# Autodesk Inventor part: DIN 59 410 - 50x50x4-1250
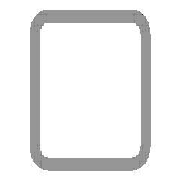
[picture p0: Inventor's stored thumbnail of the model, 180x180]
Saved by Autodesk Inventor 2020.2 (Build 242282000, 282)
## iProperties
Manager: www.cadconsulting.pl
Company: Fabian Stasiak CAD Consulting
IsCustomPart: 1
_CCFamilyMember: 40
_CCFamilyDisplayName: DIN 59410 (Kwadrat) - Rurki stalowe o przekroju kwadratowym formowane na gorąco
_FrameMemberDoc: Frame Member File
_Version: 15.0.0
_GetPNFromCC: 1
Created: 2015-01
Part Number: DIN 59 410 - 50x50x4-1250
Material: Stal, miękka
Description: Rurki stalowe o przekroju kwadratowym formowane na gorąco
Document SubType Name: Modellieren
Standard: DIN
Designer: F.Stasiak
Standards Organization: DIN
Language: pl-PL
Size Designation: 50x50x4
Categories: <MemberInstance><Categories><Category DisplayName="Kształtowniki konstrukcyjne" InternalName="089c4875-fa83-4c05-b084-43b9cc11f5ed" Mnemonic="GRDR"><CategoryPar
Stock Number: 50x50x4
Density: 7.85 g/cm^3
Appearance: Częściowo polerowana
Mass: 9798.37 g
Surface Area: 6261.29 cm^2
Volume: 1248.2 cm^3
Catalog Web Link: www.expertbooks.pl
G_W: 50,000 mm
G_H: 50,000 mm
+BD22D635-0862-4ED7-A4CA-62C603390CA0+CUTDETAIL2: Wytnij
+5BC96441-BBE8-4AF1-9985-3B583943D745+CUTDETAIL3: Wytnij
G_L: 1250,000 mm
Author: F.Stasiak
Subject: Zbiór ćwiczeń. Autodesk Inventor 2020. Kurs Professional
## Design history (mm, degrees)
node "Płaszczyzna początkowa"
node "Płaszczyzna końcowa"
sketch "Szkic1"
  geometry: L1 (-17, 25)-(17, 25); L2 (25, 17)-(25, -17); L3 (17, -25)-(-17, -25); L4 (-25, -17)-(-25, 17); L5 (-37.32, 0)-(37.32, 0) reference; L6 (0, -37.32)-(0, 37.32) reference; L7 (-17, 21)-(17, 21); L8 (21, 17)-(21, -17); L9 (17, -21)-(-17, -21); L10 (-21, -17)-(-21, 17); A1 r 8 centre (-17, 17) between (-17, 25) and (-25, 17); A2 r 8 centre (17, 17) between (25, 17) and (17, 25); A3 r 8 centre (17, -17) between (17, -25) and (25, -17); A4 r 8 centre (-17, -17) between (-25, -17) and (-17, -25); A5 r 4 centre (-17, 17) between (-17, 21) and (-21, 17); A6 r 4 centre (17, 17) between (21, 17) and (17, 21); A7 r 4 centre (17, -17) between (17, -21) and (21, -17); A8 r 4 centre (-17, -17) between (-21, -17) and (-17, -21); 3 further points
  constraints: 16 end point, 16 point on circle, 8 centre point, 8 tangent, 6 point on line, 4 parallel, 3 equal radius, 3 perpendicular, 1 horizontal, 7 other
  dimensions: "b" = 50 distance of point (-25, 25) point (25, 25); "msp_r" = 8 radius of A1 (= 2 x ParT); "d8" = 25 distance between parallel lines of L4 L6 (= d9); "d9" = 25 distance between parallel lines of L3 L5 (= 0.5 x b); "d10" = 4 distance between parallel lines of L3 L9 (= ParT)
extrude "Bryła" new body sketch "Szkic1" taper "d4" = 0 deg; stored distance "NLG" = 10
node "Driven Length"
  sketch "Sketch2"
    geometry: L1 (0, 0)-(10, 0) reference
    constraints: 2 end point, 1 horizontal
  workplane "Work Plane3"
  sketch "Sketch3"
    geometry: L1 (-2, 25)-(12, 25) reference; L2 (-2, 1275)-(12, 1275) reference
    dimensions: "d14" = 1250 distance between parallel lines of L1 L2 (derived)
node "Płaszczyzna konstrukcyjna5"
feature "Podział2"
node "Płaszczyzna konstrukcyjna6"
feature "Podział3"
body "Solid1"
other parameters: "ParT" = 4, "G_OFFSET_START" = -25 [user parameter; used in 1 equation term], "G_OFFSET_END" = -25 [user parameter; used in 1 equation term], "d11" = 25 (= -G_OFFSET_START), "d12" = 1275 (= G_OFFSET_END + B_L), "G_L" = 1250 (= d14) [user parameter], "d13" = 90 deg
